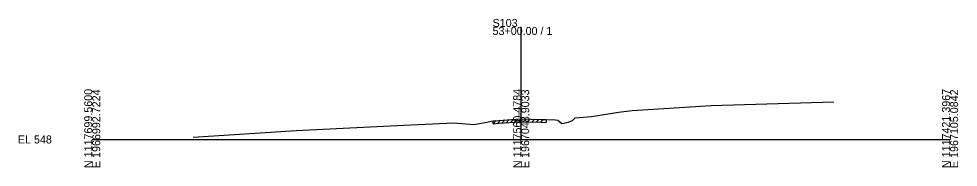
# Model space of a CAD drawing. Extents: x 974 to 1303, y 990 to 14518.
# Drawn here: x 974.3 to 1302.8, y 2490.3 to 2542.2 of the extents above; entities that cross this region are included whole.
import ezdxf

# ---------------------------------------------------------------- set-up
doc = ezdxf.new("R2010")
doc.units = 0
for name, color, linetype in [('Level 10', 7, 'Continuous'), ('Level 60', 7, 'Continuous'), ('Level 61', 7, 'Continuous'), ('Level 63', 7, 'Continuous')]:
    doc.layers.add(name, color=color, linetype=linetype)

msp = doc.modelspace()

# ---------------------------------------------------------------- linework, layer by layer
at = {"layer": 'Level 60'}
for p, q in [((1183.98, 2509.53), (1188.76, 2510.14)), ((1188.76, 2510.14), (1216.41, 2511.86)), ((1216.41, 2511.86), (1259.31, 2513.11)), ((1142.18, 2506.66), (1149.7, 2507.2)), ((1149.7, 2507.2), (1150, 2507.19)), ((1150, 2507.19), (1156.97, 2507.01)), ((1156.97, 2507.01), (1158.74, 2506.97)), ((1158.74, 2506.97), (1162.04, 2506.86)), ((1162.04, 2506.86), (1162.86, 2506.79)), ((1162.86, 2506.79), (1164.26, 2505.62)), ((1167.94, 2506.6), (1168.9, 2507.61)), ((1168.9, 2507.61), (1174.54, 2508.01)), ((1174.54, 2508.01), (1183.98, 2509.53)), ((1071.35, 2503.12), (1097.23, 2504.39)), ((1097.23, 2504.39), (1108.97, 2504.95)), ((1108.97, 2504.95), (1126.49, 2505.78)), ((1126.49, 2505.78), (1130.59, 2505.44)), ((1130.59, 2505.44), (1133.45, 2505.22)), ((1133.45, 2505.22), (1135.42, 2505.56)), ((1135.42, 2505.56), (1138.03, 2506.01)), ((1138.03, 2506.01), (1139.5, 2506.37)), ((1139.5, 2506.37), (1140.21, 2506.5)), ((1140.21, 2506.5), (1142.18, 2506.66)), ((1164.26, 2505.62), (1166.57, 2506.06)), ((1166.57, 2506.06), (1167.94, 2506.6)), ((1035.31, 2500.78), (1071.35, 2503.12))]:
    msp.add_line(p, q, dxfattribs=at)
at = {"layer": 'Level 61'}
for p, q in [((1141.71, 2505.62), (1142.79, 2506.7)), ((1143.21, 2505.73), (1144.29, 2506.81)), ((1144.71, 2505.84), (1145.79, 2506.92)), ((1146.21, 2505.95), (1147.29, 2507.03)), ((1147.71, 2506.06), (1148.79, 2507.14)), ((1149.21, 2506.17), (1150.23, 2507.19)), ((1150.71, 2506.17), (1151.69, 2507.15)), ((1152.21, 2506.14), (1153.19, 2507.11)), ((1153.71, 2506.1), (1154.69, 2507.07)), ((1155.21, 2506.06), (1156.19, 2507.03)), ((1156.71, 2506.02), (1157.69, 2507)), ((1158.74, 2506.97), (1158.74, 2505.97)), ((1140.21, 2505.5), (1141.3, 2506.59)), ((1140.21, 2505.5), (1140.21, 2506.5)), ((1140.21, 2505.5), (1142.18, 2505.66)), ((1142.18, 2505.66), (1149.7, 2506.2)), ((1149.7, 2506.2), (1150, 2506.19)), ((1150, 2506.19), (1156.97, 2506.01)), ((1156.97, 2506.01), (1158.74, 2505.97)), ((1158.74, 2505.97), (1158.74, 2505.97))]:
    msp.add_line(p, q, dxfattribs=at)
at = {"layer": 'Level 63'}
for p, q in [((1150, 2500), (1150, 2539.33)), ((1000, 2500), (1150, 2500)), ((1150, 2500), (1300, 2500))]:
    msp.add_line(p, q, dxfattribs=at)

# ---------------------------------------------------------------- texts
at = {"layer": 'Level 10'}
msp.add_text('555.19', height=0.9, rotation=90, dxfattribs=at).set_placement((1149.95, 2507.69))
at = {"layer": 'Level 63'}
for s, p in [('S103', (1140, 2539.33)), ('53+00.00 / 1', (1140, 2536.53)), ('EL 548', (974, 2498.6))]:
    msp.add_text(s, height=2.8, dxfattribs=at).set_placement(p)
for s, p in [('N 1117699.5600', (1000, 2490)), ('E 1966992.7224', (1002.8, 2490)), ('N 1117560.4784', (1150, 2490)), ('E 1967048.9033', (1152.8, 2490)), ('N 1117421.3967', (1300, 2490)), ('E 1967105.0842', (1302.8, 2490))]:
    msp.add_text(s, height=2.8, rotation=90, dxfattribs=at).set_placement(p)

doc.saveas('drawing.dxf')
